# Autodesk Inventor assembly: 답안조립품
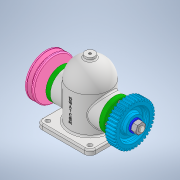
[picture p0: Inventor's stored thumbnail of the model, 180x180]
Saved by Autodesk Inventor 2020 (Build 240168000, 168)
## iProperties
Created: 2021-07
Part Number: 답안조립품
Document SubType Name: Assembly
Designer: Owner
Author: Owner
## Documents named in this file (14)
- C:\Users\Owner\Desktop\710716V1011\답안조립품.iam
- C:\Users\Owner\Desktop\710716V1011\본체.ipt
- C:\Users\Owner\Desktop\710716V1011\V-벨트풀리.ipt
- V-벨트풀리.ipt
- C:\Users\Owner\Desktop\710716V1011\너트 M12x1.25.ipt
- C:\Users\Owner\Desktop\710716V1011\베어링 6203.ipt
- C:\Users\Owner\Desktop\710716V1011\볼트 M4.ipt
- C:\Users\Owner\Desktop\710716V1011\부시.ipt
- C:\Users\Owner\Desktop\710716V1011\스퍼기어.ipt
- C:\Users\Owner\Desktop\710716V1011\오일 실 26 38 8.ipt
- C:\Users\Owner\Desktop\710716V1011\와셔 12x24.ipt
- C:\Users\Owner\Desktop\710716V1011\축.ipt
- C:\Users\Owner\Desktop\710716V1011\커버.ipt
- C:\Users\Owner\Desktop\710716V1011\키 5x5x12.ipt
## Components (1 placed, 1 different names)
1. V-벨트풀리:1
